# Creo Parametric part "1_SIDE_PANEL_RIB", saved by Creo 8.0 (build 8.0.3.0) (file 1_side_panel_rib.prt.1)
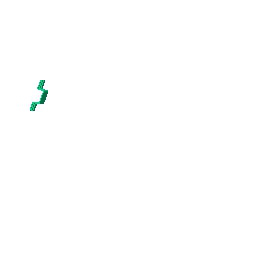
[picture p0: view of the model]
Units: millimeter Newton Second (mmNs); MM, TONNE, SECS

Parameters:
  SMT_DFLT_BEND_REL_LENGTH_TYPE = "Through All"

Other parameters: SMT_THICKNESS, SMT_PART_BEND_ALLOWANCE_FACTOR, SMT_DFLT_BEND_RADIUS, SMT_DFLT_BEND_ANGLE, SMT_DFLT_CRNR_REL_WIDTH, SMT_DFLT_CRNR_REL_DEPTH, SMT_DFLT_BEND_REL_WIDTH, SMT_DFLT_BEND_REL_DEPTH, SMT_DFLT_BEND_REL_LENGTH, SMT_DFLT_BEND_REL_ANGLE, SMT_GAP, SMT_DFLT_EDGE_TREA_WIDTH, SMT_DFLT_MITER_CUT_WIDTH, SMT_DFLT_MITER_CUT_OFFSET

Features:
  1. datum plane "DTM1"
  2. datum plane "DTM2"
  3. datum plane "DTM3"
  4. coordinate system
  5. datum plane "DTM4"
  6. datum plane "DTM5"
  7. cut
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
Other named items: CS0

Layers: 0_ALL_AXIS, 0_ALL_CSYS, 0_ALL_CURVES, 0_ALL_PLANES, 0_ALL_POINTS, 0_ALL_SURFS, 1_SIDE_PANEL_RIB

Surfaces: 36 plane, 8 cylinder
